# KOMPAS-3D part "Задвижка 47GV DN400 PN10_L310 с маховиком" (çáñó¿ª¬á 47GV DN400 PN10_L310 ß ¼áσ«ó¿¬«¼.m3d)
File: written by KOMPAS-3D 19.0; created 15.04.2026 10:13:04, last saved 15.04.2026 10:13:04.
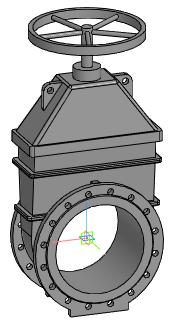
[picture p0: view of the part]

Document properties: Автор: Евгений; Полное имя файла: Z:\3.Личные\kachalov\3d для проектировщиков\2.1 Тип 47GV, 47GV.Z\Задвижка 47GV_DN40-DN600\stp_Задвижка 47GV\Задвижка 47GV DN400 PN10_L310 с маховиком.m3d

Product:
- Part/product: Задвижка 47GV DN400 PN10_L310 с маховиком

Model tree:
1. Операция без истории:1  (labels: Задвижка 47GV DN400 PN10_L310 с маховиком)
